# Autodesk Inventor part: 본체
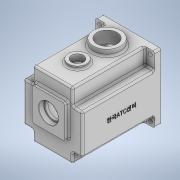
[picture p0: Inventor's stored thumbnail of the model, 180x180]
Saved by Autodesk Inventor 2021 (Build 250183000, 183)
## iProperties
Created: 2022-08
Part Number: 본체
Material: 일반
Document SubType Name: Modeling
Designer: Owner
Density: 1 g/cm^3
Appearance: 기본값
Mass: 519.917 g
Surface Area: 1178.32 cm^2
Volume: 519.917 cm^3
Author: Owner
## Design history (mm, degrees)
sketch "스케치1"
  geometry: L1 (-49, 55)-(49, 55); L2 (49, 55)-(49, -55); L3 (49, -55)-(-49, -55); L4 (-49, -55)-(-49, 55); L5 (-49, 55)-(49, -55); L6 (49, 55)-(-49, -55); 1 further point
  constraints: 12 end point, 2 midpoint, 2 parallel, 1 horizontal, 1 perpendicular
  dimensions: "d0" = 98 distance of L2.end L3.end; "d1" = 110 distance of L1.end L2.end
extrude "돌출1" new body sketch "스케치1" distance "d2" = 130; taper "d3" = 0 deg
sketch "스케치3"
  geometry: L1 (-49, -55)-(49, -55) reference; L2 (49, -55)-(49, 55) reference; L3 (49, 55)-(-49, 55) reference; L4 (-49, 55)-(49, 55) reference; L5 (33, 55)-(33, 28); L6 (33, 28)-(49, 28); L7 (49, 55)-(49, -55) reference; L8 (33, 55)-(49, 55); L9 (49, 55)-(49, 28); L10 (33, -38)-(33, -55); L11 (49, -55)-(-49, -55) reference; L12 (49, -55)-(49, -38); L13 (33, -38)-(49, -38); L14 (33, -55)-(49, -55); 4 further points
  constraints: 16 end point, 4 perpendicular, 4 point on line, 2 collinear, 1 vertical
  dimensions: "d8" = 16 distance between parallel lines of L2 L5; "d9" = 27 distance between parallel lines of L4 L6; "d12" = 17 distance between parallel lines of L1 L13; "d13" = 16 distance between parallel lines of L2 L10
extrude "돌출3" cut sketch "스케치3" distance "d14" = 120; taper "d15" = 0 deg
sketch "스케치5"
  geometry: L1 (-49, -55)-(49, -55) reference; L2 (-23, 45)-(23, 45); L3 (23, 45)-(23, 30.143); L4 (-23, 30.143)-(-23, 45); L5 (0, 0)-(0, 11.772); A1 r 42 centre (0, -5) between (-23, 30.143) and (23, 30.143)
  constraints: 8 end point, 2 point on circle, 1 centre point, 1 horizontal, 1 parallel, 1 perpendicular, 1 vertical, 1 vertical alignment, 1 other
  dimensions: "d20" = 50 distance from line of L1 A1.centre; "d21" = 46 distance between parallel lines of L3 L4; "d22" = 50 distance from line of A1.centre L2; "d23" = 42 radius of A1
extrude "돌출5" cut sketch "스케치5" distance "d24" = 121; taper "d25" = 0 deg
fillet "모깎기1" dims "d26" = 6
sketch "스케치6"
  geometry: L1 (-23, 33.249)-(-23, 45) reference; L2 (-23, 45)-(23, 45) reference; L3 (23, 45)-(23, 33.249) reference; L4 (26, 33.249)-(26, 48); L5 (26, 48)-(-26, 48); L6 (-26, 48)-(-26, 33.249); A1 r 6 centre (-29, 33.249) between (-25.375, 28.468) and (-23, 33.249) reference; A2 r 6 centre (29, 33.249) between (23, 33.249) and (25.375, 28.468) reference; A3 r 42 centre (0, -5) between (-25.375, 28.468) and (25.375, 28.468) reference; A4 r 3 centre (29, 33.249) between (26, 33.249) and (27.188, 30.859); A5 r 3 centre (-29, 33.249) between (-27.188, 30.859) and (-26, 33.249); A6 r 45 centre (0, -5) between (-27.188, 30.859) and (27.188, 30.859); 1 further point
  constraints: 6 end point, 6 point on circle, 3 centre point, 5 other
  dimensions: "d27" = 3 radial gap between concentric circles of A3 A6
extrude "돌출6" cut sketch "스케치6" distance "d28" = 9; taper "d29" = 0 deg
sketch "스케치7"
  geometry: A1 r 42 centre (0, -5) between (-25.375, 28.468) and (25.375, 28.468) reference; A2 r 15 centre (0, -25) between (-8.978, -12.984) and (8.978, -12.984); A3 r 21 centre (0, 6) between (8.978, -12.984) and (-8.978, -12.984); 1 further point
  constraints: 4 point on circle, 2 centre point, 2 vertical alignment
  dimensions: "d30" = 30 diameter of A2; "d31" = 42 diameter of A3; "d32" = 20 distance of A2.centre A1.centre; "d33" = 11 distance of A3.centre A1.centre
extrude "돌출7" join sketch "스케치7" distance "d34" = 7; taper "d35" = 0 deg
sketch "스케치8"
  geometry: A1 r 15 centre (0, -25) between (-8.978, -12.984) and (8.978, -12.984) reference; 2 further points
  constraints: 1 coincident
hole "구멍1" sketch "스케치8" at (0, -25) diameter "d36" = 19; stored, may be unused: countersink angle "d40" = 90 deg, drill point angle "d42" = 0 deg; dims "d37" = 12, "d38" = 22, "d39" = 7, "d41" = 10
sketch "스케치16"
  geometry: L1 (-33, -55)-(33, -55) reference; L2 (-27, 33)-(27, 33); L3 (27, 33)-(27, -21); L4 (27, -21)-(-27, -21); L5 (-27, -21)-(-27, 33); L6 (-27, 33)-(27, -21); L7 (27, 33)-(-27, -21); 3 further points
  constraints: 12 end point, 3 midpoint, 2 parallel, 1 horizontal, 1 perpendicular, 1 vertical alignment
  dimensions: "d79" = 54 distance of L2.start L2.end; "d80" = 54 distance of L2.end L3.end; "d81" = 61 distance from line of point (0, 6) L1
extrude "돌출13" join sketch "스케치16" distance "d82" = 7; taper "d83" = 0 deg
sketch "스케치17"
  geometry: A1 r 21 centre (0, 6) between (8.978, -12.984) and (-8.978, -12.984) reference; 2 further points
  constraints: 1 coincident
hole "구멍4" sketch "스케치17" at (0, 6) diameter "d84" = 28; stored, may be unused: countersink angle "d88" = 90 deg, drill point angle "d90" = 0 deg; dims "d85" = 12, "d86" = 35, "d87" = 10, "d89" = 10
sketch "스케치18"
  geometry: C1 r 14 at (0, 6) reference; C2 r 16 at (0, 6); 1 further point
  constraints: 1 centre point, 1 coincident
  dimensions: "d91" = 32 diameter of C2
extrude "돌출14" cut sketch "스케치18" distance "d92" = 8.3; taper "d93" = 0 deg
sketch "스케치21"
  geometry: L1 (36, -1)-(41.809, -1); L2 (36, -9)-(41.809, -9); A1 r 45 centre (0, -5) between (-27.188, 30.859) and (27.188, 30.859) reference; A2 r 42 centre (0, -5) between (-25.375, 28.468) and (25.375, 28.468) reference; A3 r 4 centre (36, -5) between (36, -1) and (36, -9); A4 r 42 centre (0, -5) between (-25.375, 28.468) and (25.375, 28.468) reference; 3 further points
  constraints: 4 end point, 4 point on circle, 2 horizontal, 2 tangent, 1 centre point, 1 horizontal alignment
  dimensions: "d101" = 8 diameter of A3; "d102" = 36 distance of A3.centre A1.centre
extrude "돌출16" join sketch "스케치21" distance "d103" = 121; taper "d104" = 0 deg
sketch "스케치22"
  geometry: L1 (82, -130)-(16, -130) reference; L2 (0, 0)-(98, 0) reference; C1 r 15 at (49, -89); 2 further points
  constraints: 1 centre point, 1 midpoint, 1 vertical alignment
  dimensions: "d105" = 30 diameter of C1; "d106" = 89 distance from line of C1.centre L2
extrude "돌출17" join sketch "스케치22" distance "d107" = 5; taper "d108" = 0 deg
sketch "스케치23"
  geometry: L1 (82, -130)-(16, -130) reference; L2 (0, 0)-(98, 0) reference; C1 r 22.5 at (49, -40); 2 further points
  constraints: 1 centre point, 1 midpoint, 1 vertical alignment
  dimensions: "d109" = 40 distance from line of C1.centre L2; "d110" = 45 diameter of C1
extrude "돌출18" join sketch "스케치23" distance "d111" = 10; taper "d112" = 0 deg
sketch "스케치25"
  geometry: C1 r 15 at (23, -32) reference; 2 further points
  constraints: 1 coincident
hole "구멍5" sketch "스케치25" at (23, -32) diameter "d113" = 20; stored, may be unused: countersink angle "d117" = 90 deg, drill point angle "d119" = 0 deg; dims "d114" = 12, "d115" = 30, "d116" = 5, "d118" = 10
sketch "스케치26"
  geometry: C1 r 22.5 at (0, 0) reference; 2 further points
  constraints: 1 coincident
hole "구멍6" sketch "스케치26" at (0, 0) diameter "d120" = 33.376; stored, may be unused: countersink angle "d124" = 90 deg, drill point angle "d126" = 0 deg; dims "d121" = 70, "d122" = 30, "d123" = 5, "d125" = 52.05
sketch "스케치27"
  geometry: A1 r 4 centre (36, -5) between (36, -1) and (36, -9) reference; 2 further points
  constraints: 1 coincident
hole "구멍7" sketch "스케치27" at (36, -5) diameter "d127" = 3.242; stored, may be unused: countersink angle "d131" = 90 deg, drill point angle "d133" = 118 deg; dims "d128" = 7, "d129" = 30, "d130" = 5, "d132" = 9
fillet "모깎기2" dims "d134" = 3
fillet "모깎기3" dims "d135" = 3
fillet "모깎기4" dims "d136" = 3
fillet "모깎기5" dims "d137" = 3
fillet "모깎기6" dims "d138" = 3
sketch "스케치28"
  geometry: L1 (49, 52)-(49, 30.196) reference; L2 (35.196, 55)-(46, 55) reference; C1 r 3.5 at (42, 48); 1 further point
  constraints: 1 centre point
  dimensions: "d139" = 7 distance from line of L2 C1.centre; "d140" = 7 distance from line of L1 C1.centre; "d141" = 7 diameter of C1
extrude "돌출19" cut sketch "스케치28" extent not by distance; stored distance "d142" = 0; taper "d143" = 0 deg
fillet "모깎기7" dims "d144" = 3
fillet "모깎기8" dims "d148" = 6
fillet "모깎기9" dims "d149" = 3
fillet "모깎기10" dims "d150" = 3
fillet "모깎기11" dims "d151" = 0.3
chamfer "모따기2" distance "d152" = 0.8; stored, may be unused: second distance "d153" = 2, angle "d154" = 30 deg
chamfer "모따기3" distance "d155" = 1; stored, may be unused: second distance "d156" = 2, angle "d157" = 30 deg
sketch "스케치29"
  geometry: L1 (-13, 107)-(-127, 107) reference; L2 (-130, 104)-(-130, 83) reference; 2 further points
  constraints: 1 other
  dimensions: "d158" = 60 distance from line of point (-65, 47) L1; "d159" = 65 distance from line of point (-65, 47) L2
feature "엠보싱1" sketch "스케치29" dims "d160" = 0.5, "d161" = 0
fillet "모깎기12" dims "d162" = 3
fillet "모깎기13" dims "d163" = 3
node "솔리드1"
mirror "미러1"
mirror "미러2"
mirror "미러3"
mirror "미러4"
mirror "미러5"
feature "A9D066F2-1C7D-4E18-AEED-F7BC21143FA4" dims "d36" = 19, "d37" = 12, "d38" = 22, "d39" = 7, "d40" = 90 deg, "d41" = 10, "d42" = 0
